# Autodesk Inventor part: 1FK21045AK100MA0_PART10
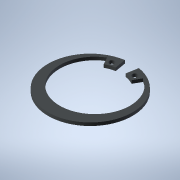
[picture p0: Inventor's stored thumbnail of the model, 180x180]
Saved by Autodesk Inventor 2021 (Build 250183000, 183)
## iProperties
Created: 2025-04
Part Number: 1FK21045AK100MA0_PART10
Material: Generic
Catalog Web Link: www.3dfindit.com
Description: -Servo synchronous motor
Document SubType Name: Modeling
Designer: psAdmin
Mass: 0.642463 g
Surface Area: 12.3927 cm^2
Volume: 0.642463 cm^3
Density: 1 g/cm^3
Appearance: PSOLRGB-212-217-219
Category: PARTsolutions
Title: 1FK21045AK100MA0_PART10
Author: Cadenas PARTsolutions
Comments: Servo synchronous motor
Sending System: PARTsolutions
Preprocessor: ST-DEVELOPER v19.3
PSOL_IDENT_0: {$CADENAS_DATA/23d-libs/siemens_ag/_cat_/e0/5f/1fk21045ak100ma0.prj},216 {VTYP=3D},{NB=1FK21045AK100
PSOL_IDENT_1: MA0_PART10},{LINA=1FK21045AK100MA0_PART10},{NN=1FK21045AK100MA0_PART10},{NOPRJ=TRUE},{DATE=19.08.202
PSOL_IDENT_2: 5 14:01:03},{GEOMDATE=30.07.2025 02:01:57},{VERSION=},{LINEID=10},{WBVAR=},{WBNUMERIC=}  {NB=1FK2104
PSOL_IDENT_3: 5AK100MA0_PART10},{LINA=1FK21045AK100MA0_PART10},{KT=DUMMY},{PREVIEW=../../../_pool_/0f/2c/p_d211_xx
PSOL_IDENT_4: _00438j.png},{DESCSHORT=SIMOTICS S-1FK2 HD, SINAMICS S210 3AC 400V-480V, 1.7 Nm, 6000 rpm},{DESCLONG=
PSOL_IDENT_5: SIMOTICS S-1FK2 HD servo motor M0=2.4 Nm; PN = 1.07 kW at nN=6000 rpm (380-480 V); PN = 0.75 kW at n
PSOL_IDENT_6: N=3000 rpm (200-240 V); with holding brake; degree of protection IP64; cylindrical shaft D19x40mm; a
PSOL_IDENT_7: bsolute encoder 22-bit + 12-bit multiturn (encoder AM22DQC); with OCC interface; plug size M17, rota
PSOL_IDENT_8: table; SIMOTICS S-1FK2 servomotorfor a wide range of uses in industrial environments. SIMOTICS S‑1FK
PSOL_IDENT_9: 2 servomotors are compact synchronous motors with a high dynamic performance that set themselves apa
PSOL_IDENT_10: rt as a result of their high power density, degree of protection and overload capability. The motors
PSOL_IDENT_11: are available in two variants: as High Dynamic variant (highest dynamic performance as a result of
PSOL_IDENT_12: the low intrinsic moment of inertia for applications demanding a high dynamic performance with low m
PSOL_IDENT_13: oved masses) - and as Compact variant (precise and stable closed-loop control for medium up to large
PSOL_IDENT_14: moved masses as a result of a medium intrinsic moment of inertia). SIMOTICSS‑1FK2 servomotors fully
PSOL_IDENT_15: exploit their strengths in a system with the SINAMICSS210 frequency converter and simple connection
PSOL_IDENT_16: using the one cable connection (OCC). Advantages include the short control and positioning times, f
PSOL_IDENT_17: ast and precise correction of disturbing quantities as well as stable control with a high dynamic pe
PSOL_IDENT_18: rformance. The servo motors can be configured to address a wide range of requirements. For example w
PSOL_IDENT_19: ith and without holding brake, IP64 or IP65 degree of protection, singleturn or multiturn absolute e
PSOL_IDENT_20: ncoders - to name just a few. Further, the servomotors are available in different shaft heights exte
PSOL_IDENT_21: nding from 20 to 100. A shaft sealing ring is available to achieve an IP65 degree of protection and
PSOL_IDENT_22: for subsequent mounting at the motor or as spare part. SIMOTICS - the optimum motor for each and eve
PSOL_IDENT_23: ry motion control application.},{INTNO=804766807114},{SUPPLIERALTNO=1FK2104-5AK10-0MA0},{MANUID=1FK2
PSOL_IDENT_24: 1045AK100MA0},{MANUNAME=Siemens},{MANUTYPEDESC=Synchronous motor 1FK2-HD 2,39 Nm},{AAU732=SIMOTICS},
PSOL_IDENT_25: {AAO057=S-1FK2},{AAU734=SIMOTICS S-1FK2 HD servo motor M0=2.4 Nm; PN = 1.07 kW at nN=6000 rpm (380-4
PSOL_IDENT_26: 80 V); PN = 0.75 kW at nN=3000 rpm (200-240 V); with holding brake; degree of protection IP64; cylin
PSOL_IDENT_27: drical shaft D19x40mm; absolute encoder 22-bit + 12-bit multiturn (encoder AM22DQC); with OCC interf
PSOL_IDENT_28: ace; plug size M17, rotatable;},{AAW338=Synchronous motor 1FK2-HD 2,39 Nm},{AAO742=SIMOTICS},{AAO663=
PSOL_IDENT_29: 4042948691236},{NOCUPEROU=1},{PRICEQUANTITY=1},{QUANTITYMIN=1},{QUANTITYINT=1},{CTN=85015100},{COO=D
PSOL_IDENT_30: E},{AAO676=1FK2104-5AK10-0MA0},{AAO677=Siemens AG},{ORDERUNIT=C62},{CONTENTUNIT=C62}
NB: 1FK21045AK100MA0_PART10
NT: Servo synchronous motor
NBSYN: $MANUID._PART10
LINA: 1FK21045AK100MA0_PART10
CATALOG: SIEMENS
PREVIEW: ../../../_pool_/0f/2c/p_d211_xx_00438j.png
DESCSHORT: SIMOTICS S-1FK2 HD, SINAMICS S210 3AC 400V-480V, 1.7 Nm, 6000 rpm
DESCLONG: SIMOTICS S-1FK2 HD servo motor M0=2.4 Nm; PN = 1.07 kW at nN=6000 rpm (380-480 V); PN = 0.75 kW at nN=3000 rpm (200-240 V); with holding brake; degree of protec
INTNO: 804766807114
SUPPLIERALTNO: 1FK2104-5AK10-0MA0
MANUID: 1FK21045AK100MA0
MANUNAME: Siemens
MANUTYPEDESC: Synchronous motor 1FK2-HD 2,39 Nm
AAU732: SIMOTICS
AAO057: S-1FK2
AAU734: SIMOTICS S-1FK2 HD servo motor M0=2.4 Nm; PN = 1.07 kW at nN=6000 rpm (380-480 V); PN = 0.75 kW at nN=3000 rpm (200-240 V); with holding brake; degree of protec
AAW338: Synchronous motor 1FK2-HD 2,39 Nm
AAO742: SIMOTICS
AAO663: 4042948691236.0
NOCUPEROU: 1
PRICEQUANTITY: 1
QUANTITYMIN: 1
QUANTITYINT: 1
CTN: 85015100
COO: DE
ARTICLENO: 1FK21045AK100MA0_PART10
BOMINFO: 1FK21045AK100MA0_PART10
CREATOR: CADENAS GmbH
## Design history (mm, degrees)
feature "2025_04_17_15_45_15_0090"
body "Solid1"
